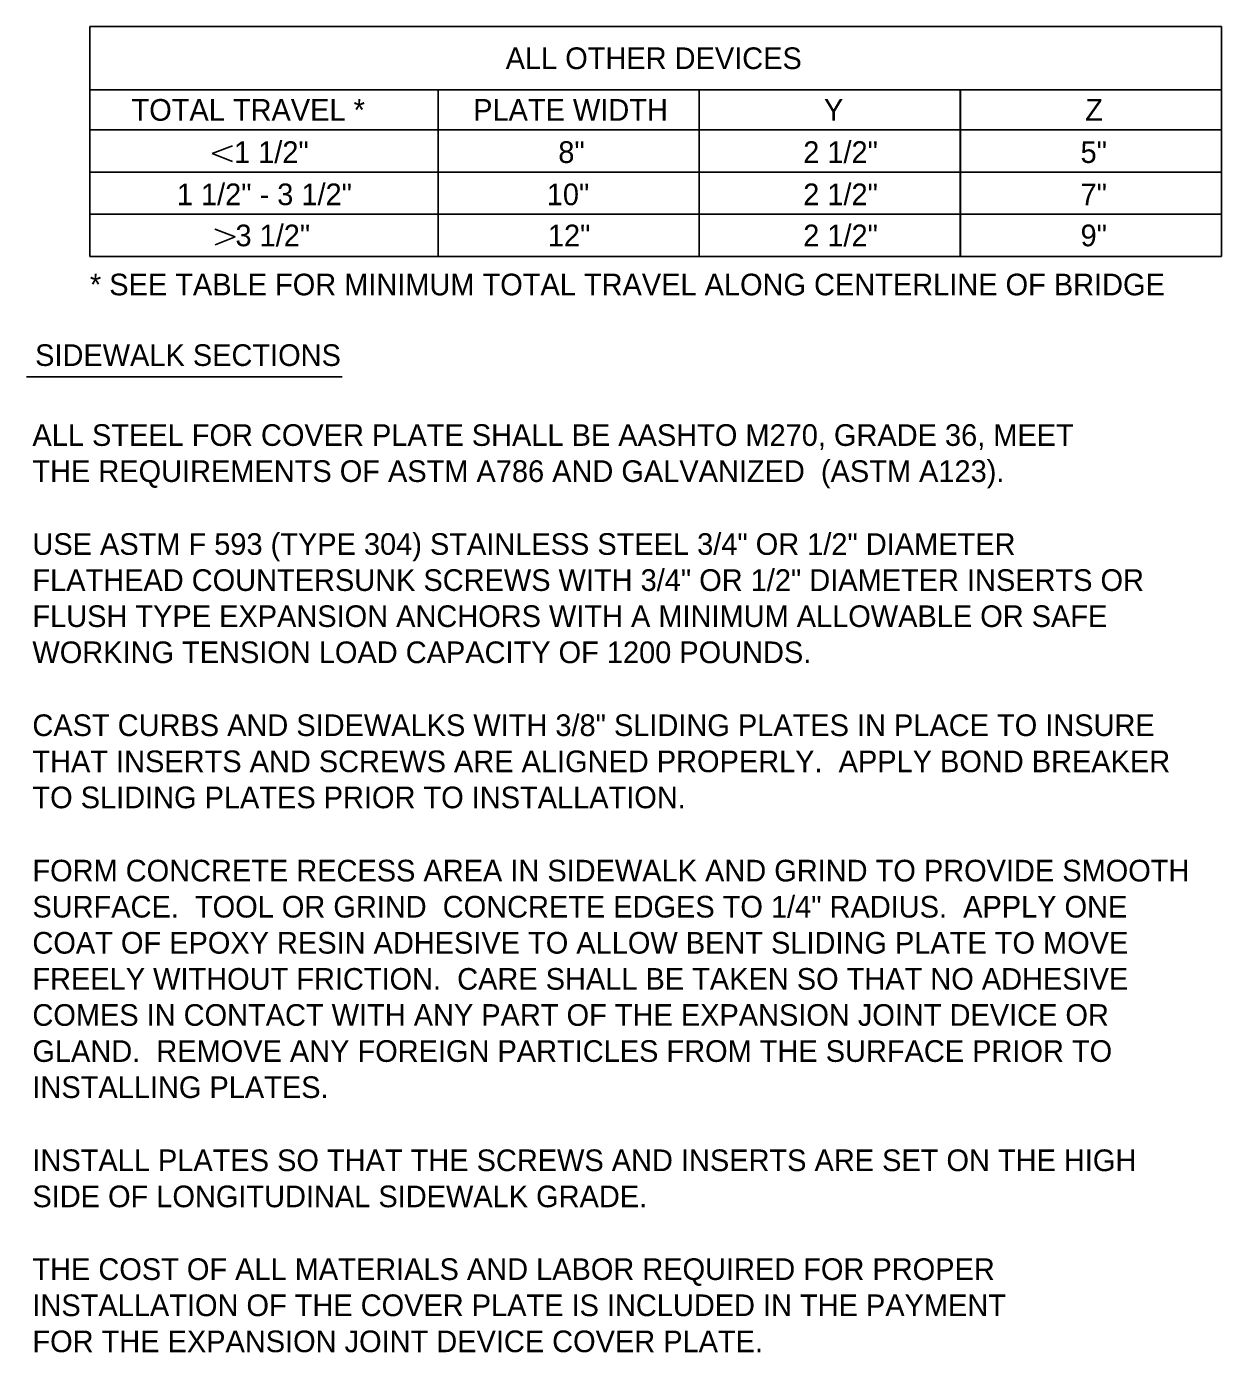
# Model space of a CAD drawing. Extents: x 19590 to 20151, y 19944 to 20103.
# Drawn here: x 19879.5 to 19906.96, y 20018.3 to 20048.77 of the extents above; entities that cross this region are included whole.
import ezdxf

# ---------------------------------------------------------------- set-up
doc = ezdxf.new("R2010")
doc.units = 0
for name, color, linetype in [('DETAIL_TEXT_DIMEN_PR', 7, 'Continuous'), ('Level 1', 7, 'Continuous'), ('MT_PAVT_MRKGS_EX_REF', 7, 'Continuous'), ('PAVT_MRKGS_QUANT', 7, 'Continuous')]:
    doc.layers.add(name, color=color, linetype=linetype)

# ---------------------------------------------------------------- blocks, each defined once
blk = doc.blocks.new('TERM')
at = {"layer": 'DETAIL_TEXT_DIMEN_PR'}
for p, q in [((-0.0388, -0.01), (0, 0)), ((0, 0), (-0.0387, 0.01))]:
    blk.add_line(p, q, dxfattribs=at)
blk = doc.blocks.new('EJ3H')
at = {"layer": 'MT_PAVT_MRKGS_EX_REF'}
for p, q in [((69.331, -47.335), (69.331, -52.621)), ((69.331, -47.335), (95.331, -47.335)), ((95.331, -47.335), (95.331, -52.621)), ((69.34, -48.792), (95.331, -48.792)), ((77.331, -48.792), (77.331, -52.621)), ((83.331, -48.792), (83.331, -52.621)), ((89.331, -48.792), (89.331, -52.621)), ((69.322, -49.708), (95.331, -49.708)), ((69.331, -50.679), (95.331, -50.679)), ((69.331, -51.65), (95.331, -51.65)), ((69.331, -52.621), (95.331, -52.621)), ((67.875, -55.384), (75.123, -55.384))]:
    blk.add_line(p, q, dxfattribs=at)
at = {"layer": 'PAVT_MRKGS_QUANT', "xscale": 12, "yscale": 18, "rotation": 180}
blk.add_blockref('TERM', (72.143, -50.255), dxfattribs=at)
at = {"layer": 'PAVT_MRKGS_QUANT', "xscale": 12, "yscale": -18}
blk.add_blockref('TERM', (72.671, -52.17), dxfattribs=at)
at = {"layer": 'MT_PAVT_MRKGS_EX_REF'}
for s, height, p in [('ALL OTHER DEVICES', 0.49762, (78.884, -48.312)), ('TOTAL TRAVEL *', 0.49762, (70.287, -49.499)), ('PLATE WIDTH', 0.49762, (78.137, -49.499)), ('Y', 0.498, (86.197, -49.499)), ('Z', 0.498, (92.201, -49.499)), ('  1 1/2"', 0.4976, (72.273, -50.47)), ('8"', 0.4976, (80.094, -50.47)), ('2 1/2"', 0.4976, (85.721, -50.47)), ('5"', 0.4976, (92.094, -50.47)), ('1 1/2" - 3 1/2"', 0.49762, (71.328, -51.44)), ('10"', 0.4976, (79.829, -51.44)), ('2 1/2"', 0.4976, (85.721, -51.44)), ('7"', 0.4976, (92.094, -51.44)), ('  3 1/2"', 0.4976, (72.306, -52.384)), ('12"', 0.4976, (79.854, -52.384)), ('2 1/2"', 0.4976, (85.721, -52.384)), ('9"', 0.4976, (92.094, -52.384)), ('SIDEWALK SECTIONS', 0.49762, (68.073, -55.135))]:
    blk.add_text(s, height=height, rotation=0, dxfattribs=at).set_placement(p)
for s, p in [('* SEE TABLE FOR MINIMUM TOTAL TRAVEL ALONG CENTERLINE OF BRIDGE', (69.331, -53.512)), ('ALL STEEL FOR COVER PLATE SHALL BE AASHTO M270, GRADE 36, MEET', (68.01, -56.972)), ('THE REQUIREMENTS OF ASTM A786 AND GALVANIZED  (ASTM A123).', (68.01, -57.801)), ('USE ASTM F 593 (TYPE 304) STAINLESS STEEL 3/4" OR 1/2" DIAMETER ', (68.01, -59.476)), ('FLATHEAD COUNTERSUNK SCREWS WITH 3/4" OR 1/2" DIAMETER INSERTS OR ', (68.01, -60.305)), ('FLUSH TYPE EXPANSION ANCHORS WITH A MINIMUM ALLOWABLE OR SAFE ', (68.01, -61.134)), ('WORKING TENSION LOAD CAPACITY OF 1200 POUNDS.', (68.01, -61.964)), ('CAST CURBS AND SIDEWALKS WITH 3/8" SLIDING PLATES IN PLACE TO INSURE ', (68.01, -63.64)), ('THAT INSERTS AND SCREWS ARE ALIGNED PROPERLY.  APPLY BOND BREAKER', (68.01, -64.47)), ('TO SLIDING PLATES PRIOR TO INSTALLATION.', (68.01, -65.299)), ('FORM CONCRETE RECESS AREA IN SIDEWALK AND GRIND TO PROVIDE SMOOTH ', (68.01, -66.982)), ('SURFACE.  TOOL OR GRIND  CONCRETE EDGES TO 1/4" RADIUS.  APPLY ONE ', (68.01, -67.811)), ('COAT OF EPOXY RESIN ADHESIVE TO ALLOW BENT SLIDING PLATE TO MOVE ', (68.01, -68.64)), ('FREELY WITHOUT FRICTION.  CARE SHALL BE TAKEN SO THAT NO ADHESIVE ', (68.01, -69.47)), ('COMES IN CONTACT WITH ANY PART OF THE EXPANSION JOINT DEVICE OR ', (68.01, -70.299)), ('GLAND.  REMOVE ANY FOREIGN PARTICLES FROM THE SURFACE PRIOR TO ', (68.01, -71.128)), ('INSTALLING PLATES.', (68.01, -71.958)), ('INSTALL PLATES SO THAT THE SCREWS AND INSERTS ARE SET ON THE HIGH ', (68.01, -73.638)), ('SIDE OF LONGITUDINAL SIDEWALK GRADE.', (68.01, -74.468)), ('THE COST OF ALL MATERIALS AND LABOR REQUIRED FOR PROPER ', (68.01, -76.14)), ('INSTALLATION OF THE COVER PLATE IS INCLUDED IN THE PAYMENT ', (68.01, -76.97)), ('FOR THE EXPANSION JOINT DEVICE COVER PLATE.', (68.01, -77.799))]:
    blk.add_text(s, height=0.49762, dxfattribs=at).set_placement(p)

msp = doc.modelspace()

# ---------------------------------------------------------------- linework, layer by layer
at = {"layer": 'MT_PAVT_MRKGS_EX_REF'}
for p, q in [((19880.956, 20048.772), (19880.956, 20043.485)), ((19880.956, 20048.772), (19906.956, 20048.772)), ((19906.956, 20048.772), (19906.956, 20043.485)), ((19880.965, 20047.314), (19906.956, 20047.314)), ((19888.956, 20047.314), (19888.956, 20043.485)), ((19894.956, 20047.314), (19894.956, 20043.485)), ((19900.956, 20047.314), (19900.956, 20043.485)), ((19880.946, 20046.398), (19906.956, 20046.398)), ((19880.956, 20045.427), (19906.956, 20045.427)), ((19880.956, 20044.456), (19906.956, 20044.456)), ((19880.956, 20043.485), (19906.956, 20043.485)), ((19879.499, 20040.722), (19886.748, 20040.722))]:
    msp.add_line(p, q, dxfattribs=at)

# ---------------------------------------------------------------- block references
at = {"layer": 'Level 1'}
msp.add_blockref('EJ3H', (19811.624, 20096.106), dxfattribs=at)
at = {"layer": 'PAVT_MRKGS_QUANT', "xscale": 12, "yscale": 18, "rotation": 180}
msp.add_blockref('TERM', (19883.767, 20045.851), dxfattribs=at)
at = {"layer": 'PAVT_MRKGS_QUANT', "xscale": 12, "yscale": -18}
msp.add_blockref('TERM', (19884.296, 20043.936), dxfattribs=at)

# ---------------------------------------------------------------- texts
at = {"layer": 'MT_PAVT_MRKGS_EX_REF'}
for s, height, p in [('ALL OTHER DEVICES', 0.49762, (19890.508, 20047.794)), ('TOTAL TRAVEL *', 0.49762, (19881.912, 20046.607)), ('PLATE WIDTH', 0.49762, (19889.762, 20046.607)), ('Y', 0.498, (19897.822, 20046.607)), ('Z', 0.498, (19903.825, 20046.607)), ('  1 1/2"', 0.4976, (19883.897, 20045.637)), ('8"', 0.4976, (19891.718, 20045.637)), ('2 1/2"', 0.4976, (19897.345, 20045.637)), ('5"', 0.4976, (19903.718, 20045.637)), ('1 1/2" - 3 1/2"', 0.49762, (19882.952, 20044.666)), ('10"', 0.4976, (19891.453, 20044.666)), ('2 1/2"', 0.4976, (19897.345, 20044.666)), ('7"', 0.4976, (19903.718, 20044.666)), ('  3 1/2"', 0.4976, (19883.93, 20043.722)), ('12"', 0.4976, (19891.478, 20043.722)), ('2 1/2"', 0.4976, (19897.345, 20043.722)), ('9"', 0.4976, (19903.718, 20043.722)), ('SIDEWALK SECTIONS', 0.49762, (19879.697, 20040.971))]:
    msp.add_text(s, height=height, rotation=0, dxfattribs=at).set_placement(p)
for s, p in [('* SEE TABLE FOR MINIMUM TOTAL TRAVEL ALONG CENTERLINE OF BRIDGE', (19880.956, 20042.594)), ('ALL STEEL FOR COVER PLATE SHALL BE AASHTO M270, GRADE 36, MEET', (19879.635, 20039.134)), ('THE REQUIREMENTS OF ASTM A786 AND GALVANIZED  (ASTM A123).', (19879.635, 20038.305)), ('USE ASTM F 593 (TYPE 304) STAINLESS STEEL 3/4" OR 1/2" DIAMETER ', (19879.635, 20036.63)), ('FLATHEAD COUNTERSUNK SCREWS WITH 3/4" OR 1/2" DIAMETER INSERTS OR ', (19879.635, 20035.801)), ('FLUSH TYPE EXPANSION ANCHORS WITH A MINIMUM ALLOWABLE OR SAFE ', (19879.635, 20034.972)), ('WORKING TENSION LOAD CAPACITY OF 1200 POUNDS.', (19879.635, 20034.142)), ('CAST CURBS AND SIDEWALKS WITH 3/8" SLIDING PLATES IN PLACE TO INSURE ', (19879.635, 20032.466)), ('THAT INSERTS AND SCREWS ARE ALIGNED PROPERLY.  APPLY BOND BREAKER', (19879.635, 20031.636)), ('TO SLIDING PLATES PRIOR TO INSTALLATION.', (19879.635, 20030.807)), ('FORM CONCRETE RECESS AREA IN SIDEWALK AND GRIND TO PROVIDE SMOOTH ', (19879.635, 20029.125)), ('SURFACE.  TOOL OR GRIND  CONCRETE EDGES TO 1/4" RADIUS.  APPLY ONE ', (19879.635, 20028.295)), ('COAT OF EPOXY RESIN ADHESIVE TO ALLOW BENT SLIDING PLATE TO MOVE ', (19879.635, 20027.466)), ('FREELY WITHOUT FRICTION.  CARE SHALL BE TAKEN SO THAT NO ADHESIVE ', (19879.635, 20026.636)), ('COMES IN CONTACT WITH ANY PART OF THE EXPANSION JOINT DEVICE OR ', (19879.635, 20025.807)), ('GLAND.  REMOVE ANY FOREIGN PARTICLES FROM THE SURFACE PRIOR TO ', (19879.635, 20024.978)), ('INSTALLING PLATES.', (19879.635, 20024.148)), ('INSTALL PLATES SO THAT THE SCREWS AND INSERTS ARE SET ON THE HIGH ', (19879.635, 20022.468)), ('SIDE OF LONGITUDINAL SIDEWALK GRADE.', (19879.635, 20021.638)), ('THE COST OF ALL MATERIALS AND LABOR REQUIRED FOR PROPER ', (19879.635, 20019.966)), ('INSTALLATION OF THE COVER PLATE IS INCLUDED IN THE PAYMENT ', (19879.635, 20019.136)), ('FOR THE EXPANSION JOINT DEVICE COVER PLATE.', (19879.635, 20018.307))]:
    msp.add_text(s, height=0.49762, dxfattribs=at).set_placement(p)

doc.saveas('drawing.dxf')
